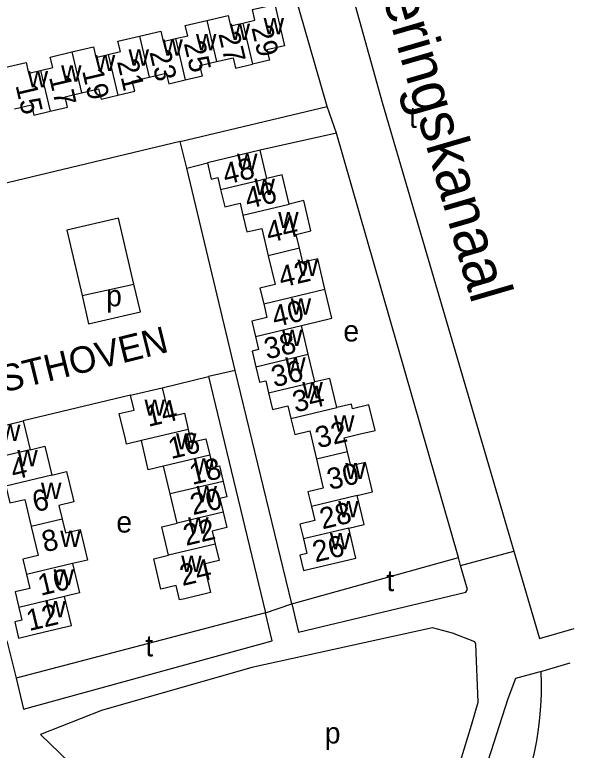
# Model space of a CAD drawing. Extents: x 157646 to 159241, y 379213 to 381217.
# Drawn here: x 159135.3 to 159240.8, y 380481.3 to 380620.1 of the extents above; entities that cross this region are included whole.
import ezdxf

# ---------------------------------------------------------------- set-up
doc = ezdxf.new("R2010")
doc.units = 0
for name, color, linetype in [('BLT_Basislijn', 7, 'Continuous'), ('BLT_Bebouwing', 7, 'Continuous'), ('BLT_Centroide', 7, 'Continuous'), ('BLT_Huisnummer', 7, 'Continuous'), ('BLT_Huisnummer_ tussenligend', 7, 'Continuous'), ('BLT_Onderverdeling_panden', 7, 'Continuous'), ('BLT_Straatnaam', 7, 'Continuous'), ('BLT_Waternaam_spoorwegen', 7, 'Continuous')]:
    doc.layers.add(name, color=color, linetype=linetype)

msp = doc.modelspace()

# ---------------------------------------------------------------- linework, layer by layer
at = {"layer": 'BLT_Basislijn'}
for p, q in [((159195.96, 380597.72), (159194.21, 380602.73)), ((159167.72, 380591.12), (159166.48, 380596.15)), ((159167.72, 380591.12), (159171.6, 380592.12)), ((159176.86, 380552.98), (159167.72, 380591.12)), ((159145.08, 380579.43), (159147.95, 380567.12)), ((159147.95, 380567.12), (159157.75, 380569.24)), ((159176.86, 380552.98), (159171.82, 380551.81)), ((159187.55, 380508.95), (159176.86, 380552.98)), ((159163.09, 380549.71), (159171.82, 380551.81)), ((159171.82, 380551.81), (159182.55, 380507.28)), ((159157.07, 380548.29), (159136.85, 380543.44)), ((159219.37, 380516.17), (159229.39, 380518.89)), ((159187.55, 380508.95), (159218.94, 380517.67)), ((159182.55, 380507.28), (159187.55, 380508.95)), ((159182.55, 380507.28), (159135.52, 380494.92)), ((159234.23, 380502.39), (159240.81, 380504.29)), ((159234.5, 380496.21), (159240.02, 380497.81)), ((159234.21, 380496.12), (159234.5, 380496.21))]:
    msp.add_line(p, q, dxfattribs=at)
for points in [[(159171.34, 380722.55), (159174.47, 380707.52), (159187.04, 380666.49), (159204.66, 380603.29)], [(159194.21, 380602.73), (159179.5, 380653.84)], [(159204.66, 380603.29), (159229.39, 380518.89)], [(159166.48, 380596.15), (159194.21, 380602.73)], [(159195.96, 380597.72), (159181.57, 380594.49)], [(159218.94, 380517.67), (159195.96, 380597.72)], [(159166.48, 380596.15), (159132.57, 380588.05), (159131.93, 380587.91)], [(159157.75, 380569.24), (159154.85, 380581.71), (159145.08, 380579.43)], [(159147.95, 380567.12), (159149.2, 380561.73), (159158.97, 380564), (159157.75, 380569.24)], [(159229.39, 380518.89), (159234.23, 380502.39)], [(159219.37, 380516.17), (159218.94, 380517.67)], [(159187.55, 380508.95), (159188.79, 380503.6), (159220.35, 380511.15), (159220.67, 380511.63), (159219.37, 380516.17)], [(159135.52, 380494.92), (159136.94, 380489.07), (159183.83, 380501.96), (159182.55, 380507.28)], [(159221.43, 380486.08), (159222.67, 380490.41), (159222.26, 380501.35), (159222.04, 380501.77), (159217.81, 380503.41), (159214.08, 380504.44), (159179.96, 380496.96), (159151.63, 380488.82), (159140.13, 380484.3), (159151.01, 380473.8), (159165.12, 380468.24), (159173.74, 380461.75), (159182.65, 380456.36), (159187.9, 380456.5), (159205.5, 380463.37), (159217.26, 380472.5), (159221.43, 380486.08)], [(159133.77, 380501.99), (159135.52, 380494.92)], [(159220.45, 380460.92), (159219.78, 380462.39), (159219.65, 380464.07), (159228.32, 380491.1), (159229.81, 380494.9), (159234.21, 380496.12)], [(159234.5, 380496.21), (159234.56, 380494.01), (159234.54, 380491.82), (159234.44, 380489.62), (159234.26, 380487.43), (159234, 380485.25), (159233.66, 380483.08), (159233.25, 380480.92), (159232.75, 380478.78), (159232.18, 380476.66), (159231.53, 380474.56), (159230.8, 380472.49), (159230.6, 380471.94)]]:
    msp.add_lwpolyline(points, dxfattribs=at)
at = {"layer": 'BLT_Bebouwing'}
for p, q in [((159181.57, 380594.49), (159171.6, 380592.12)), ((159182.83, 380589.17), (159181.57, 380594.49)), ((159190.63, 380556.03), (159189.34, 380561.47)), ((159191.87, 380550.81), (159190.63, 380556.03)), ((159157.07, 380548.29), (159163.09, 380549.71)), ((159126.89, 380541.07), (159136.85, 380543.44)), ((159136.85, 380543.44), (159138.14, 380538.02)), ((159164.59, 380529.67), (159163.34, 380534.93)), ((159165.9, 380524.17), (159164.59, 380529.67))]:
    msp.add_line(p, q, dxfattribs=at)
for points in [[(159178.27, 380618.49), (159180.57, 380619.03), (159180.1, 380621.03), (159184.3, 380622.01), (159186.13, 380614.21), (159182.84, 380613.43), (159183.3, 380611.48), (159180.09, 380610.73)], [(159171.48, 380618.96), (159175.51, 380619.91), (159175.97, 380617.95), (159178.27, 380618.49)], [(159165.59, 380615.55), (159167.89, 380616.09), (159167.44, 380618.01), (159171.48, 380618.96)], [(159152.88, 380612.56), (159155.19, 380613.1), (159154.73, 380615.1), (159158.77, 380616.04)], [(159158.77, 380616.04), (159162.82, 380616.99), (159163.29, 380615.01), (159165.59, 380615.55)], [(159140.15, 380609.55), (159142.42, 380610.08), (159141.96, 380612.07), (159146.04, 380613.03)], [(159146.04, 380613.03), (159150.12, 380613.98), (159150.58, 380612.02), (159152.88, 380612.56)], [(159173.29, 380611.23), (159176.44, 380611.96), (159176.9, 380609.98), (159180.09, 380610.73)], [(159133.42, 380610.11), (159134.14, 380610.28), (159137.41, 380611.05), (159137.88, 380609.02), (159140.15, 380609.55)], [(159167.41, 380607.78), (159170.65, 380608.54), (159170.2, 380610.5), (159173.29, 380611.23)], [(159160.6, 380608.27), (159163.84, 380609.03), (159164.3, 380607.05), (159167.41, 380607.78)], [(159154.69, 380604.87), (159157.89, 380605.62), (159157.44, 380607.53), (159160.6, 380608.27)], [(159147.85, 380605.31), (159151.08, 380606.07), (159151.54, 380604.14), (159154.69, 380604.87)], [(159141.96, 380601.85), (159145.23, 380602.62), (159144.77, 380604.59), (159147.85, 380605.31)], [(159135.24, 380602.33), (159138.39, 380603.07), (159138.85, 380601.12), (159141.96, 380601.85)], [(159171.6, 380592.12), (159172.33, 380589.05), (159173.56, 380589.34), (159174.09, 380587.09)], [(159187.02, 380584.34), (159185.71, 380589.85), (159182.83, 380589.17)], [(159174.09, 380587.09), (159174.87, 380583.84), (159177.76, 380584.52), (159178.29, 380582.27)], [(159188.96, 380576), (159188.33, 380578.63), (159191.13, 380579.3), (159189.78, 380585), (159187.02, 380584.34)], [(159178.29, 380582.27), (159179.05, 380579.09), (159181.86, 380579.76), (159183.08, 380574.61)], [(159193.78, 380568.29), (159192.41, 380574.05), (159189.58, 380573.38), (159188.96, 380576)], [(159183.08, 380574.61), (159184.38, 380569.15), (159181.52, 380568.47), (159182.22, 380565.54)], [(159189.34, 380561.47), (159192.25, 380562.16), (159195.08, 380562.83), (159193.78, 380568.29)], [(159182.22, 380565.54), (159182.84, 380562.94), (159179.97, 380562.26), (159180.65, 380559.4)], [(159180.65, 380559.4), (159181.24, 380556.89), (159180.05, 380556.6), (159180.74, 380553.68)], [(159180.74, 380553.68), (159181.43, 380550.75), (159182.61, 380551.03), (159183.15, 380548.74)], [(159196.01, 380545.96), (159194.7, 380551.48), (159191.87, 380550.81)], [(159163.09, 380549.71), (159164.39, 380544.25), (159167.26, 380544.93), (159167.99, 380541.85)], [(159159.15, 380539.75), (159156.36, 380539.09), (159156.14, 380539.98), (159154.99, 380544.84), (159157.77, 380545.5), (159157.07, 380548.29)], [(159183.15, 380548.74), (159183.89, 380545.63), (159186.78, 380546.32), (159187.35, 380543.9)], [(159198.02, 380537.6), (159197.38, 380540.26), (159200.15, 380540.92), (159203.22, 380541.67), (159202.08, 380546.46), (159199, 380545.73), (159198.79, 380546.61), (159196.01, 380545.96)], [(159187.35, 380543.9), (159188.07, 380540.87), (159190.91, 380541.55), (159192.18, 380536.22)], [(159167.99, 380541.85), (159168.57, 380539.42), (159171.33, 380540.07), (159172.06, 380537)], [(159163.34, 380534.93), (159160.46, 380534.24), (159159.15, 380539.75)], [(159138.14, 380538.02), (159140.92, 380538.68), (159142.23, 380533.21)], [(159172.06, 380537), (159172.61, 380534.68), (159173.89, 380534.99), (159174.58, 380532.05)], [(159199.87, 380529.36), (159202.74, 380530.05), (159201.41, 380535.6), (159198.65, 380534.95), (159198.02, 380537.6)], [(159192.18, 380536.22), (159193.47, 380530.79), (159190.55, 380530.1), (159191.22, 380527.31)], [(159142.23, 380533.21), (159145.05, 380533.88), (159146.21, 380529.02), (159146.4, 380528.19), (159143.58, 380527.52), (159144.2, 380524.92)], [(159133.56, 380531.15), (159134.31, 380527.98), (159137.14, 380528.65), (159138.36, 380523.53)], [(159174.58, 380532.05), (159175.28, 380529.11), (159173.97, 380528.8), (159174.58, 380526.24)], [(159198.29, 380523.24), (159201.16, 380523.92), (159199.87, 380529.36)], [(159191.22, 380527.31), (159191.85, 380524.65), (159189.06, 380523.98), (159189.72, 380521.21)], [(159174.58, 380526.24), (159175.27, 380523.32), (159172.48, 380522.66), (159173.06, 380520.21)], [(159144.2, 380524.92), (159144.82, 380522.31), (159147.63, 380522.98), (159149, 380517.21), (159146.18, 380516.54)], [(159164.29, 380518.12), (159163.02, 380523.49), (159165.9, 380524.17)], [(159138.36, 380523.53), (159139.66, 380518.04), (159136.8, 380517.36), (159137.48, 380514.47)], [(159189.72, 380521.21), (159190.38, 380518.45), (159189.07, 380518.14), (159189.76, 380515.23), (159199.63, 380517.58), (159198.29, 380523.24)], [(159173.06, 380520.21), (159173.8, 380517.11), (159170.92, 380516.43), (159172.19, 380511.08), (159167.33, 380509.92), (159166.33, 380509.69), (159165.69, 380512.38), (159162.84, 380511.7), (159161.47, 380517.46), (159164.29, 380518.12)], [(159146.18, 380516.54), (159147.5, 380511), (159144.66, 380510.33)], [(159137.48, 380514.47), (159138.1, 380511.87), (159135.32, 380511.21), (159136.02, 380508.27)], [(159136.02, 380508.27), (159136.6, 380505.84), (159135.26, 380505.53), (159135.98, 380502.49), (159140.85, 380503.65), (159145.96, 380504.87), (159144.66, 380510.33)]]:
    msp.add_lwpolyline(points, dxfattribs=at)
at = {"layer": 'BLT_Onderverdeling_panden'}
for p, q in [((159171.48, 380618.96), (159173.29, 380611.23)), ((159178.27, 380618.49), (159180.09, 380610.73)), ((159158.77, 380616.04), (159160.6, 380608.27)), ((159165.59, 380615.55), (159167.41, 380607.78)), ((159146.04, 380613.03), (159147.85, 380605.31)), ((159152.88, 380612.56), (159154.69, 380604.87)), ((159140.15, 380609.55), (159141.96, 380601.85)), ((159174.09, 380587.09), (159182.83, 380589.17)), ((159178.29, 380582.27), (159187.02, 380584.34)), ((159188.96, 380576), (159183.08, 380574.61)), ((159182.22, 380565.54), (159193.78, 380568.29)), ((159180.65, 380559.4), (159189.34, 380561.47)), ((159180.74, 380553.68), (159190.63, 380556.03)), ((159183.15, 380548.74), (159191.87, 380550.81)), ((159187.35, 380543.9), (159196.01, 380545.96)), ((159167.99, 380541.85), (159159.15, 380539.75)), ((159138.14, 380538.02), (159129.43, 380535.95)), ((159172.06, 380537), (159163.34, 380534.93)), ((159198.02, 380537.6), (159192.18, 380536.22)), ((159142.23, 380533.21), (159133.56, 380531.15)), ((159174.58, 380532.05), (159164.59, 380529.67)), ((159199.87, 380529.36), (159191.22, 380527.31)), ((159174.58, 380526.24), (159165.9, 380524.17)), ((159144.2, 380524.92), (159138.36, 380523.53)), ((159198.29, 380523.24), (159189.72, 380521.21)), ((159173.06, 380520.21), (159164.29, 380518.12)), ((159146.18, 380516.54), (159137.48, 380514.47)), ((159144.66, 380510.33), (159136.02, 380508.27))]:
    msp.add_line(p, q, dxfattribs=at)

# ---------------------------------------------------------------- texts
at = {"layer": 'BLT_Centroide'}
for s, p in [('w', (159182.2, 380616.38)), ('w', (159175.78, 380615.28)), ('w', (159169.44, 380613.36)), ('w', (159163.09, 380612.34)), ('w', (159156.73, 380610.45)), ('w', (159150.36, 380609.42)), ('w', (159144, 380607.45)), ('w', (159137.69, 380606.38)), ('t', (159209.66, 380598.72)), ('w', (159177.18, 380590.78)), ('w', (159180.48, 380586.06)), ('w', (159184.95, 380579.81)), ('w', (159188.59, 380570.78)), ('p', (159152.5, 380565.07)), ('w', (159187.31, 380563.5)), ('w', (159185.67, 380557.56)), ('e', (159197.25, 380558.43)), ('w', (159186.27, 380552.38)), ('w', (159189.51, 380547.69)), ('w', (159159.73, 380544.41)), ('w', (159195.48, 380541.41)), ('w', (159132.48, 380539.69)), ('w', (159165.68, 380538.06)), ('w', (159135.74, 380534.91)), ('w', (159169, 380533.34)), ('w', (159197.61, 380532.47)), ('w', (159140.21, 380528.72)), ('w', (159169.55, 380528.12)), ('w', (159196.27, 380525.28)), ('e', (159154.42, 380522.39)), ('w', (159167.96, 380522.19)), ('w', (159143.84, 380519.69)), ('w', (159194.71, 380519.25)), ('w', (159166.66, 380514.94)), ('w', (159142.57, 380512.41)), ('t', (159205.36, 380511.34)), ('w', (159141.03, 380506.41)), ('t', (159159.9, 380499.03)), ('p', (159193.74, 380482.61))]:
    msp.add_text(s, height=4, dxfattribs=at).set_placement(p)
at = {"layer": 'BLT_Huisnummer'}
for s, rotation, p in [('29', 283.2007, (159179.88, 380617.62)), ('25', 283.2007, (159167.13, 380614.67)), ('21', 283.2007, (159154.53, 380611.24)), ('17', 283.2007, (159141.71, 380608.31)), ('48', 13.3629, (159175.02, 380587.98)), ('42', 13.3629, (159185.58, 380568.56)), ('38', 13.3629, (159182.84, 380555.02)), ('34', 13.3629, (159188.19, 380545.02)), ('14', 13.3808, (159160.44, 380542.31)), ('18', 13.3746, (159168.74, 380531.35)), ('30', 13.3629, (159194.7, 380530.4)), ('6', 13.3916, (159139.11, 380526.2)), ('26', 13.3629, (159191.96, 380516.74)), ('24', 13.3803, (159166.89, 380512.29)), ('12', 13.3748, (159137.98, 380503.8))]:
    msp.add_text(s, height=4, rotation=rotation, dxfattribs=at).set_placement(p)
at = {"layer": 'BLT_Huisnummer_ tussenligend'}
for s, rotation, p in [('27', 283.2007, (159173.65, 380616.46)), ('23', 283.2007, (159160.65, 380613.01)), ('19', 283.2007, (159147.94, 380609.49)), ('15', 283.2007, (159135.38, 380606.75)), ('46', 13.3629, (159179.2, 380583.39)), ('44', 13.3629, (159183.2, 380577.01)), ('40', 13.3629, (159184.31, 380561.1)), ('36', 13.3629, (159184.19, 380549.77)), ('32', 13.3629, (159192.49, 380538.26)), ('16', 13.3808, (159164.74, 380536.23)), ('4', 13.376, (159135.02, 380532.29)), ('20', 13.3746, (159168.89, 380525.65)), ('28', 13.3629, (159193.3, 380522.98)), ('22', 13.3746, (159167.57, 380519.87)), ('8', 13.3916, (159140.9, 380518.64)), ('10', 13.3916, (159140.15, 380510.45))]:
    msp.add_text(s, height=4, rotation=rotation, dxfattribs=at).set_placement(p)
at = {"layer": 'BLT_Straatnaam'}
msp.add_text('RUSTHOVEN', height=5, rotation=13.8399, dxfattribs=at).set_placement((159123.77, 380546.47))
at = {"layer": 'BLT_Waternaam_spoorwegen'}
msp.add_text('Afwateringskanaal', height=7.9999, rotation=286.2296, dxfattribs=at).set_placement((159197.14, 380649.23))

doc.saveas('drawing.dxf')
